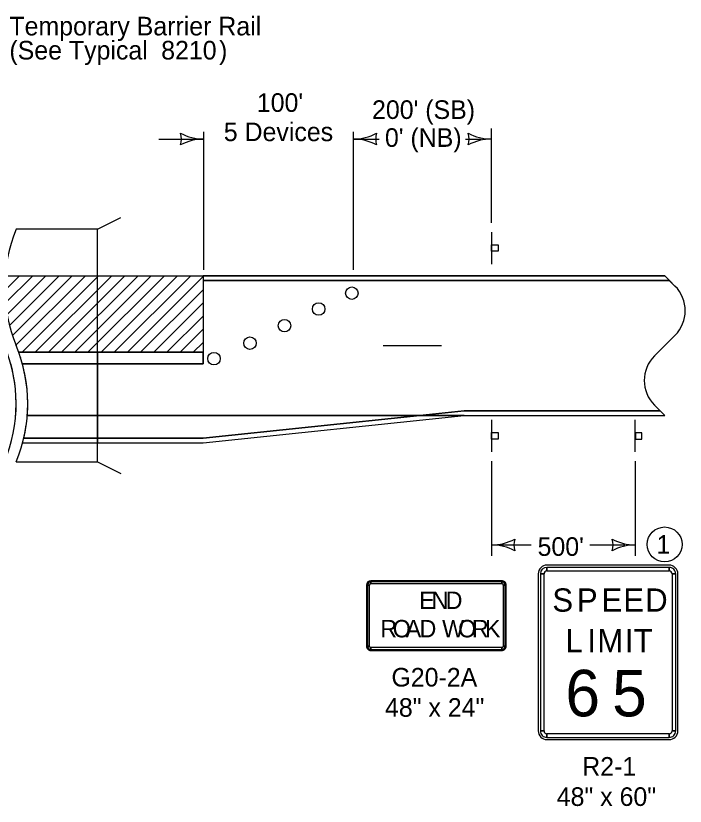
# Model space of a CAD drawing. Extents: x 10124 to 16850, y 7924 to 12166.
# Drawn here: x 12678 to 13254, y 8907 to 9587 of the extents above; entities that cross this region are included whole.
import ezdxf

# ---------------------------------------------------------------- set-up
doc = ezdxf.new("R2010")
doc.units = 0
for name, color, linetype in [('dsnShtPlotShapeBatchPrint', 7, 'Continuous'), ('dsnStdLabel', 7, 'Continuous'), ('dsnStdLineWork', 7, 'Continuous'), ('dsnStdShading', 7, 'Continuous'), ('SheetText', 7, 'Continuous')]:
    doc.layers.add(name, color=color, linetype=linetype)

msp = doc.modelspace()

# ---------------------------------------------------------------- linework, layer by layer
at = {"layer": 'dsnShtPlotShapeBatchPrint'}
msp.add_circle((13235.81, 9132.08), 15, dxfattribs=at)
at = {"layer": 'dsnStdLabel'}
for p, q in [((13087, 9400.58), (13087, 9373.08)), ((12668.66, 9350.06), (12681.64, 9363.04)), ((12669.34, 9339.43), (12692.95, 9363.04)), ((12670.77, 9329.54), (12704.27, 9363.04)), ((12672.82, 9320.28), (12715.58, 9363.04)), ((12675.42, 9311.57), (12726.89, 9363.04)), ((12678.5, 9303.34), (12738.21, 9363.04)), ((12683.79, 9297.31), (12749.52, 9363.04)), ((12695.1, 9297.31), (12760.83, 9363.04)), ((12706.41, 9297.31), (12772.15, 9363.04)), ((12717.73, 9297.31), (12783.46, 9363.04)), ((12729.04, 9297.31), (12794.78, 9363.04)), ((12740.35, 9297.31), (12806.09, 9363.04)), ((12751.67, 9297.31), (12817.4, 9363.04)), ((12762.98, 9297.31), (12828.72, 9363.04)), ((12774.3, 9297.31), (12839.39, 9362.4)), ((12839.39, 9363.04), (12839.39, 9297.31)), ((12785.61, 9297.31), (12839.39, 9351.09)), ((12796.92, 9297.31), (12839.39, 9339.77)), ((12808.24, 9297.31), (12839.39, 9328.46)), ((12819.55, 9297.31), (12839.39, 9317.15)), ((12830.86, 9297.31), (12839.39, 9305.83)), ((12748.62, 9297.31), (12748.62, 9287.31)), ((12839.39, 9287.31), (12839.39, 9297.31)), ((12748.62, 9287.31), (12839.39, 9287.31)), ((12839.39, 9223.54), (13063.59, 9247.04)), ((13063.59, 9247.04), (13231.94, 9247.04)), ((13087, 9239.13), (13087, 9211.63)), ((13210.63, 9211.63), (13210.63, 9239.13)), ((13239.73, 9114.28), (13134.73, 9114.28)), ((13134.73, 9109.28), (13134.73, 9112.4)), ((13239.73, 9112.4), (13239.73, 9109.28)), ((13127.23, 9106.78), (13127.23, 8971.78)), ((13129.1, 9106.78), (13132.23, 9106.78)), ((13242.23, 9106.78), (13245.35, 9106.78)), ((13247.23, 8971.78), (13247.23, 9106.78)), ((13095.9, 9100.93), (12983.4, 9100.93)), ((12983.4, 9098.43), (12983.4, 9099.99)), ((13095.9, 9099.99), (13095.9, 9098.43)), ((12979.65, 9097.18), (12979.65, 9044.68)), ((12980.59, 9097.18), (12982.15, 9097.18)), ((13097.15, 9097.18), (13098.71, 9097.18)), ((13099.65, 9044.68), (13099.65, 9097.18)), ((12982.15, 9044.68), (12980.59, 9044.68)), ((13098.71, 9044.68), (13097.15, 9044.68)), ((12983.4, 9041.87), (12983.4, 9043.43)), ((12983.4, 9040.93), (13095.9, 9040.93)), ((13095.9, 9043.43), (13095.9, 9041.87)), ((13132.23, 8971.78), (13129.1, 8971.78)), ((13245.35, 8971.78), (13242.23, 8971.78)), ((13134.73, 8966.16), (13134.73, 8969.28)), ((13134.73, 8964.28), (13239.73, 8964.28)), ((13239.73, 8969.28), (13239.73, 8966.16))]:
    msp.add_line(p, q, dxfattribs=at)
for points in [[(13087.09, 9384.13), (13087.09, 9389.76), (13092.72, 9389.76), (13092.72, 9384.13)], [(13087.09, 9222.68), (13087.09, 9228.31), (13092.72, 9228.31), (13092.72, 9222.68)], [(13210.73, 9228.08), (13210.73, 9222.46), (13216.35, 9222.46), (13216.35, 9228.08)], [(13239.73, 9112.4), (13134.73, 9112.4), (13134.73, 9109.28), (13239.73, 9109.28), (13239.73, 9112.4)], [(13129.1, 9106.78), (13129.1, 8971.78), (13132.23, 8971.78), (13132.23, 9106.78), (13129.1, 9106.78)], [(13245.35, 8971.78), (13245.35, 9106.78), (13242.23, 9106.78), (13242.23, 8971.78), (13245.35, 8971.78)], [(13095.9, 9099.99), (12983.4, 9099.99), (12983.4, 9098.43), (13095.9, 9098.43), (13095.9, 9099.99)], [(12980.59, 9097.18), (12980.59, 9044.68), (12982.15, 9044.68), (12982.15, 9097.18), (12980.59, 9097.18)], [(13098.71, 9044.68), (13098.71, 9097.18), (13097.15, 9097.18), (13097.15, 9044.68), (13098.71, 9044.68)], [(12983.4, 9041.87), (13095.9, 9041.87), (13095.9, 9043.43), (12983.4, 9043.43), (12983.4, 9041.87)], [(13134.73, 8966.16), (13239.73, 8966.16), (13239.73, 8969.28), (13134.73, 8969.28), (13134.73, 8966.16)]]:
    msp.add_lwpolyline(points, close=True, dxfattribs=at)
msp.add_lwpolyline([(12839.39, 9297.31), (12830.86, 9297.31), (12819.55, 9297.31), (12808.24, 9297.31), (12796.92, 9297.31), (12785.61, 9297.31), (12774.3, 9297.31), (12762.98, 9297.31), (12751.67, 9297.31), (12748.62, 9297.31)], dxfattribs=at)
for centre in [(12967.11, 9348.08), (12967.11, 9348.08), (12938.52, 9334.47), (12938.52, 9334.47), (12909.19, 9320.16), (12909.19, 9320.16), (12879.57, 9305.06), (12879.57, 9305.06), (12848.61, 9291.84), (12848.61, 9291.84)]:
    msp.add_circle(centre, 5.37, dxfattribs=at)
for centre, radius, start, end in [((13134.73, 9106.78), 7.5, 90.00021, 179.99985), ((13134.73, 9106.78), 5.62, 90.00021, 179.99985), ((13239.73, 9106.78), 7.5, 0, 90.00021), ((13239.73, 9106.78), 5.62, 0, 90.00021), ((13134.73, 9106.78), 2.5, 90.00021, 179.99985), ((13239.73, 9106.78), 2.5, 0, 90.00021), ((12983.4, 9097.18), 3.75, 90.00021, 179.99985), ((12983.4, 9097.18), 2.81, 90.00021, 179.99985), ((13095.9, 9097.18), 3.75, 0, 90.00021), ((13095.9, 9097.18), 2.81, 0, 90.00021), ((12983.4, 9097.18), 1.25, 90.00021, 179.99985), ((13095.9, 9097.18), 1.25, 0, 90.00021), ((12983.4, 9044.68), 3.75, 179.99985, 270.00006), ((12983.4, 9044.68), 2.81, 179.99985, 270.00006), ((12983.4, 9044.68), 1.25, 179.99985, 270.00006), ((13095.9, 9044.68), 3.75, 270.00006, 0.00027), ((13095.9, 9044.68), 2.81, 270.00006, 0.00027), ((13095.9, 9044.68), 1.25, 270.00006, 0.00027), ((13134.73, 8971.78), 7.5, 179.99985, 270.00006), ((13134.73, 8971.78), 5.62, 179.99985, 270.00006), ((13134.73, 8971.78), 2.5, 179.99985, 270.00006), ((13239.73, 8971.78), 7.5, 270.00006, 0.00027), ((13239.73, 8971.78), 5.62, 270.00006, 0.00027), ((13239.73, 8971.78), 2.5, 270.00006, 0.00027)]:
    msp.add_arc(centre, radius, start, end, dxfattribs=at)
at = {"layer": 'dsnStdLineWork'}
for p, q in [((12748.62, 9403.04), (12768.62, 9413.04)), ((13244.73, 9354.25), (13235.94, 9363.04)), ((13227.15, 9294.26), (13244.73, 9311.83)), ((12680.86, 9297.31), (12839.39, 9297.31)), ((12839.39, 9297.31), (12839.39, 9287.31)), ((12839.39, 9287.31), (12684.03, 9287.31)), ((13235.94, 9243.04), (13227.15, 9251.83)), ((12688.24, 9243.04), (13063.61, 9243.04)), ((12839.39, 9223.54), (13063.59, 9247.04)), ((12685.23, 9223.54), (12839.39, 9223.54)), ((12678.63, 9203.04), (12748.62, 9203.04)), ((12748.62, 9203.04), (12768.62, 9193.04))]:
    msp.add_line(p, q, dxfattribs=at)
for points in [[(12748.62, 9203.04), (12748.62, 9403.04), (12678.63, 9403.04)], [(12839.39, 9359.04), (13239.94, 9359.04)], [(12994.05, 9303.04), (13044.05, 9303.04)], [(12994.05, 9303.04), (13044.05, 9303.04)], [(12680.86, 9297.31), (12693.92, 9297.31)], [(12697.09, 9287.31), (12684.03, 9287.31)], [(13063.59, 9247.04), (13231.94, 9247.04)]]:
    msp.add_lwpolyline(points, dxfattribs=at)
for centre, radius, start, end in [((12798.62, 9353.04), 130, 157.38014, 202.61987), ((13223.51, 9333.04), 30, 315.00015, 44.99873), ((12548.63, 9253.04), 130, 337.38014, 22.61987), ((12558.63, 9253.04), 130, 337.38014, 22.61987), ((13248.36, 9273.04), 30, 135, 225)]:
    msp.add_arc(centre, radius, start, end, dxfattribs=at)
at = {"layer": 'dsnStdShading'}
for p, q in [((12669.01, 9363.04), (13235.94, 9363.04)), ((13235.94, 9363.04), (12839.39, 9363.04)), ((12839.39, 9363.04), (12839.39, 9359.04)), ((12839.39, 9359.04), (13239.94, 9359.04)), ((13239.94, 9359.04), (12839.39, 9359.04)), ((12839.39, 9359.04), (12839.39, 9351.09)), ((13239.94, 9359.04), (13235.94, 9363.04)), ((13244.72, 9354.26), (13239.94, 9359.04)), ((12839.39, 9351.09), (12839.39, 9339.77)), ((12839.39, 9339.77), (12839.39, 9328.46)), ((13227.15, 9294.26), (13244.72, 9311.83)), ((12748.62, 9287.31), (12748.62, 9297.31)), ((12839.39, 9297.31), (12839.39, 9287.31)), ((12684.03, 9287.31), (12697.09, 9287.31)), ((12697.09, 9287.31), (12748.62, 9287.31)), ((12748.62, 9243.04), (12748.62, 9287.31)), ((12839.39, 9287.31), (12748.62, 9287.31)), ((12748.62, 9287.31), (12748.62, 9243.04)), ((13231.94, 9247.04), (13227.15, 9251.83)), ((12748.62, 9243.04), (12688.24, 9243.04)), ((12688.24, 9243.04), (12748.62, 9243.04)), ((12981.78, 9243.04), (12748.62, 9243.04)), ((12748.62, 9243.04), (12748.62, 9223.54)), ((12748.62, 9223.54), (12748.62, 9243.04)), ((12748.62, 9243.04), (13025.44, 9243.04)), ((12839.39, 9219.54), (13063.59, 9243.04)), ((12839.39, 9223.54), (13025.43, 9243.04)), ((12839.39, 9219.54), (13063.59, 9243.04)), ((13025.43, 9243.04), (12839.39, 9223.54)), ((12981.78, 9243.04), (13235.94, 9243.04)), ((13025.43, 9243.04), (12981.78, 9243.04)), ((13063.59, 9247.04), (13025.43, 9243.04)), ((13063.59, 9243.04), (13025.43, 9243.04)), ((13025.43, 9243.04), (13235.94, 9243.04)), ((13025.44, 9243.04), (13063.59, 9247.04)), ((13231.94, 9247.04), (13063.59, 9247.04)), ((13063.59, 9247.04), (13231.94, 9247.04)), ((13235.94, 9243.04), (13231.94, 9247.04)), ((12685.23, 9223.54), (12698.3, 9223.54)), ((12698.3, 9223.54), (12685.23, 9223.54)), ((12698.3, 9223.54), (12748.62, 9223.54)), ((12748.62, 9223.54), (12698.3, 9223.54)), ((12748.62, 9223.54), (12839.39, 9223.54)), ((12839.39, 9223.54), (12748.62, 9223.54)), ((12748.62, 9223.54), (12748.62, 9219.54)), ((12748.62, 9219.54), (12748.62, 9223.54)), ((12684.23, 9219.54), (12748.62, 9219.54)), ((12684.23, 9219.54), (12839.39, 9219.54)), ((12684.23, 9219.54), (12697.3, 9219.54)), ((12748.62, 9219.54), (12839.39, 9219.54))]:
    msp.add_line(p, q, dxfattribs=at)
for points in [[(13239.94, 9359.04), (13239.94, 9359.04)], [(13239.94, 9359.04), (13239.94, 9359.04)], [(12839.39, 9328.46), (12839.39, 9317.15), (12839.39, 9305.83), (12839.39, 9297.31)], [(12748.62, 9297.31), (12740.35, 9297.31), (12729.04, 9297.31), (12717.73, 9297.31), (12706.41, 9297.31), (12695.1, 9297.31), (12693.92, 9297.31), (12683.79, 9297.31), (12680.86, 9297.31)], [(12748.62, 9287.31), (12697.09, 9287.31), (12684.03, 9287.31)], [(12981.78, 9243.04), (12981.78, 9243.04)], [(13231.94, 9247.04), (13231.94, 9247.04)], [(13231.94, 9247.04), (13231.94, 9247.04)]]:
    msp.add_lwpolyline(points, dxfattribs=at)
for centre, radius, start, end in [((13223.51, 9333.04), 30, 315, 45), ((12558.63, 9253.04), 130, 15.28322, 19.90817), ((13248.36, 9273.04), 30, 135, 225), ((12548.63, 9253.04), 130, 355.58827, 15.28231), ((12558.63, 9253.04), 130, 355.58916, 15.28322), ((12558.63, 9253.04), 130, 346.88255, 355.58916), ((12558.63, 9253.04), 130, 345.06535, 346.88255)]:
    msp.add_arc(centre, radius, start, end, dxfattribs=at)
at = {"layer": 'SheetText'}
for p, q in [((12839.92, 9368.09), (12839.92, 9486.8)), ((12968.41, 9368.09), (12968.41, 9486.8)), ((13087, 9408.58), (13087, 9489.79)), ((12801.13, 9480.57), (12839.98, 9480.57)), ((12968.41, 9480.57), (12990.58, 9480.57)), ((13064.65, 9480.57), (13078.13, 9480.57)), ((13087, 9203.63), (13087, 9122.43)), ((13210.63, 9203.63), (13210.63, 9122.43)), ((13087.12, 9131.64), (13121.16, 9131.64)), ((13171.58, 9131.64), (13201.77, 9131.64))]:
    msp.add_line(p, q, dxfattribs=at)
for centre, radius, start, end in [((12804.34, 9480.57), 16.42, 342.26665, 17.73335), ((12839.98, 9523.07), 42.5, 241.92751, 270), ((12839.98, 9438.07), 42.5, 90, 118.07249), ((12968.35, 9523.07), 42.5, 270, 298.07249), ((12968.35, 9438.07), 42.5, 61.92751, 90), ((13003.99, 9480.57), 16.42, 162.26665, 197.73335), ((13051.43, 9480.57), 16.42, 342.26665, 17.73335), ((13087.07, 9523.07), 42.5, 241.92751, 270), ((13087.07, 9438.07), 42.5, 90, 118.07249), ((13087.07, 9174.14), 42.5, 270, 298.07249), ((13122.7, 9131.64), 16.42, 162.26665, 197.73335), ((13175.07, 9131.64), 16.42, 342.26665, 17.73335), ((13210.7, 9174.14), 42.5, 241.92751, 270), ((13087.07, 9089.15), 42.5, 61.92751, 90), ((13210.7, 9089.14), 42.5, 90, 118.07249)]:
    msp.add_arc(centre, radius, start, end, dxfattribs=at)

# ---------------------------------------------------------------- texts
at = {"layer": 'dsnShtPlotShapeBatchPrint'}
msp.add_text('1', height=16, dxfattribs=at).set_placement((13228.83, 9124.08))
at = {"layer": 'dsnStdLabel'}
for s, height, p in [('S', 20, (13139.36, 9074.28)), ('P', 20, (13160.45, 9074.28)), ('E', 20, (13181.54, 9074.28)), ('E', 20, (13200.35, 9074.28)), ('D', 20, (13219.16, 9074.28)), ('E', 15, (13024.98, 9076.55)), ('N', 15, (13035.6, 9076.55)), ('D', 15, (13047.68, 9076.55)), ('R', 15, (12991.51, 9052.18)), ('O', 15, (13002.2, 9052.18)), ('A', 15, (13013.35, 9052.18)), ('D', 15, (13025.21, 9052.18)), ('W', 15, (13044.66, 9052.18)), ('O', 15, (13058.4, 9052.18)), ('R', 15, (13070.16, 9052.18)), ('K', 15, (13081.46, 9052.18)), ('L', 20, (13150.61, 9039.28)), ('I', 20, (13169.42, 9039.28)), ('M', 20, (13178.01, 9039.28)), ('I', 20, (13201.6, 9039.28)), ('T', 20, (13209.16, 9039.28)), ('6', 40, (13150.61, 8984.28)), ('5', 40, (13190.73, 8984.28))]:
    msp.add_text(s, height=height, dxfattribs=at).set_placement(p)
at = {"layer": 'SheetText'}
for s, p in [('Temporary Barrier Rail', (12672.86, 9569.7)), ('(See Typical ', (12672.86, 9548.99)), ('8210', (12803.28, 9548.99)), (')', (12852.99, 9548.99)), ("100'", (12885.47, 9503.96)), ("200' (SB)", (12984.45, 9497.89)), ('5 Devices', (12857.08, 9478.81)), ("0' (NB)", (12995.53, 9473.89)), ("500'", (13126.68, 9122.25)), ('G20-2A', (13001.12, 9009.93)), ('48" x 24"', (12995.59, 8983.93)), ('R2-1', (13165.06, 8933.28)), ('48" x 60"', (13143.16, 8907.28))]:
    msp.add_text(s, height=16, dxfattribs=at).set_placement(p)

doc.saveas('drawing.dxf')
